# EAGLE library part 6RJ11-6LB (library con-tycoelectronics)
CORCOM Modular RJ Jacks L - Ganged Series Source: www.tycoelectronics.com .. ENG_DS_1654001_1099_RJ_L_0507.pdf
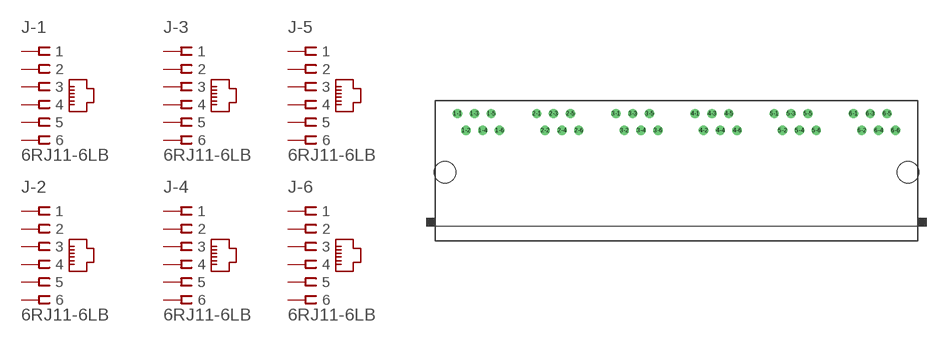
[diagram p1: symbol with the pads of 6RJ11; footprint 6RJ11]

Designator prefix J; gates -1=JACK6 -2=JACK6 -3=JACK6 -4=JACK6 -5=JACK6 -6=JACK6

## 6RJ11-6LB (MPN: 6RJ11-6L-B; OC_FARNELL: unknown; OC_NEWARK: 19R5426)  [6RJ11]
1-1  -1:1  pas
1-2  -1:2  pas
1-3  -1:3  pas
1-4  -1:4  pas
1-5  -1:5  pas
1-6  -1:6  pas
2-1  -2:1  pas
2-2  -2:2  pas
2-3  -2:3  pas
2-4  -2:4  pas
2-5  -2:5  pas
2-6  -2:6  pas
3-1  -3:1  pas
3-2  -3:2  pas
3-3  -3:3  pas
3-4  -3:4  pas
3-5  -3:5  pas
3-6  -3:6  pas
4-1  -4:1  pas
4-2  -4:2  pas
4-3  -4:3  pas
4-4  -4:4  pas
4-5  -4:5  pas
4-6  -4:6  pas
5-1  -5:1  pas
5-2  -5:2  pas
5-3  -5:3  pas
5-4  -5:4  pas
5-5  -5:5  pas
5-6  -5:6  pas
6-1  -6:1  pas
6-2  -6:2  pas
6-3  -6:3  pas
6-4  -6:4  pas
6-5  -6:5  pas
6-6  -6:6  pas

## Footprint 6RJ11 (pad centres in mm)
RJ11 x 6 Source: www.tycoelectronics.com .. ENG_DS_1654001_1099_RJ_L_0507.pdf
drill 0.9 pad 1.4 round: 1-1 -33.02,8.89; 1-2 -31.75,6.35; 1-3 -30.48,8.89; 1-4 -29.21,6.35; 1-5 -27.94,8.89; 1-6 -26.67,6.35; 2-1 -21.082,8.89; 2-2 -19.812,6.35; 2-3 -18.542,8.89; 2-4 -17.272,6.35; 2-5 -16.002,8.89; 2-6 -14.732,6.35; 3-1 -9.144,8.89; 3-2 -7.874,6.35; 3-3 -6.604,8.89; 3-4 -5.334,6.35; 3-5 -4.064,8.89; 3-6 -2.794,6.35; 4-1 2.794,8.89; 4-2 4.064,6.35; 4-3 5.334,8.89; 4-4 6.604,6.35; 4-5 7.874,8.89; 4-6 9.144,6.35; 5-1 14.732,8.89; 5-2 16.002,6.35; 5-3 17.272,8.89; 5-4 18.542,6.35; 5-5 19.812,8.89; 5-6 21.082,6.35; 6-1 26.67,8.89; 6-2 27.94,6.35; 6-3 29.21,8.89; 6-4 30.48,6.35; 6-5 31.75,8.89; 6-6 33.02,6.35
hole 3.251 at -34.925,0
hole 3.251 at 34.925,0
